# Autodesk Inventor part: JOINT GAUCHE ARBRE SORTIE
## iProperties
Created: 2004-11
Part Number: JOINT GAUCHE ARBRE SORTIE
Document SubType Name: Modeling
Designer: Bruno
Manufacturer: Standard
Standards Organization: Custom
Author: Bruno
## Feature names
1. Base1
